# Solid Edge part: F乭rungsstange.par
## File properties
Username: bmolnar
Dokumentum tartalom típus: 0
Author: bmolnar
Last saved by: bmolnar
Revision: 84
Sűrűség: 0,000 kg/m^3
Pontosság: 0,990
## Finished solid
Body 1: solid body, 8 faces, 7 edges, 1 vertex.
  Faces by surface: cone 4, cylinder 2, plane 2
  Edges by curve: circle 7
Bounding box of the edges (mm): 85.000 x 14.000 x 14.000, from (0, -7, -7) to (85, 7, 7).
Cylindrical faces by radius (mm): R3.3235 x1, R7 x1
Conical faces (half-angle, radius in mm at the cone's reference point): 45 deg R3.6235 x1, 45 deg R6.9 x1, 45 deg R7 x1, 59 deg R1.6618 x1
Planar faces by outward normal: +x 1, -x 1
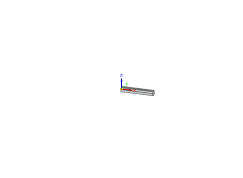
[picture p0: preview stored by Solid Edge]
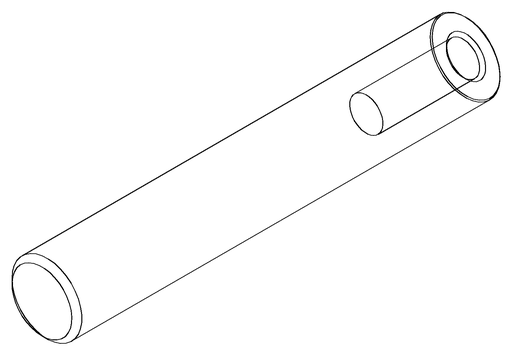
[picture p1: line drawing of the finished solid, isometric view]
